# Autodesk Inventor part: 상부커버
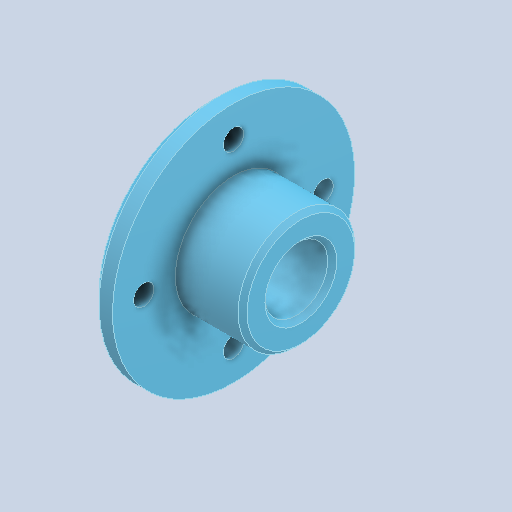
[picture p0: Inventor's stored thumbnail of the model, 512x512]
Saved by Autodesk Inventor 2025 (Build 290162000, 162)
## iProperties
Created: 2024-07
Part Number: 상부커버
Material: 알루미늄 6061
Document SubType Name: Modeling
Designer: Administrator
Density: 2.71 g/cm^3
Appearance: 기본값
Author: jhkim
Sending System: Autodesk Inventor 2025
Preprocessor: ST-DEVELOPER v20
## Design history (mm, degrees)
feature "솔리드1"
node "솔리드2"
